// Mitsubishi GX Works2 project: MC-18MR-10MTS-F430-H3G-A例程   PLC: FX3G

PROGRAM MAIN
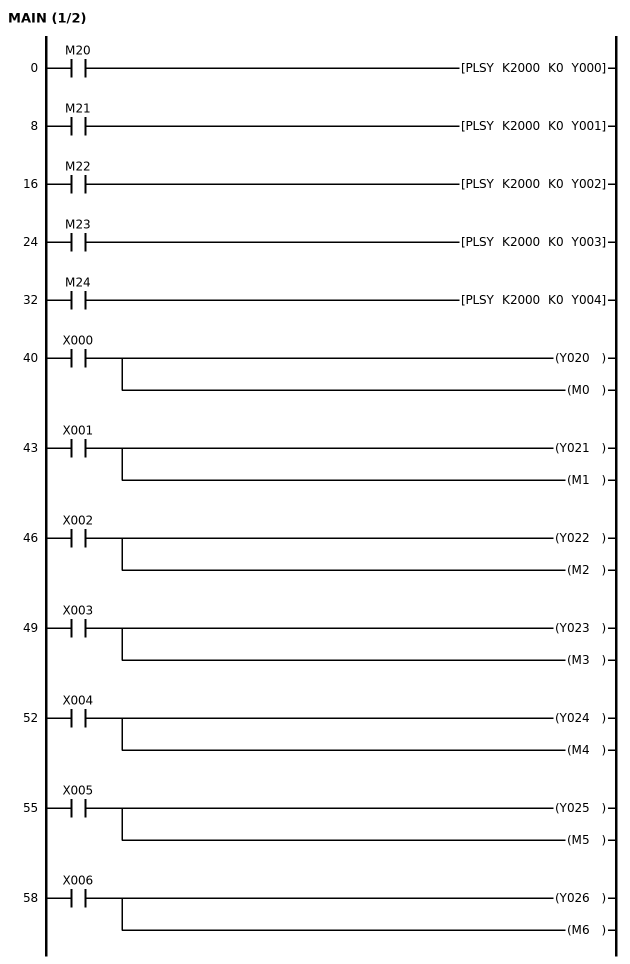
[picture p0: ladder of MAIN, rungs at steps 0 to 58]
0     LD      M20
      PLSY    K2000 K0 Y000
8     LD      M21
      PLSY    K2000 K0 Y001
16    LD      M22
      PLSY    K2000 K0 Y002
24    LD      M23
      PLSY    K2000 K0 Y003
32    LD      M24
      PLSY    K2000 K0 Y004
40    LD      X000
      OUT     Y020
      OUT     M0
43    LD      X001
      OUT     Y021
      OUT     M1
46    LD      X002
      OUT     Y022
      OUT     M2
49    LD      X003
      OUT     Y023
      OUT     M3
52    LD      X004
      OUT     Y024
      OUT     M4
55    LD      X005
      OUT     Y025
      OUT     M5
58    LD      X006
      OUT     Y026
      OUT     M6
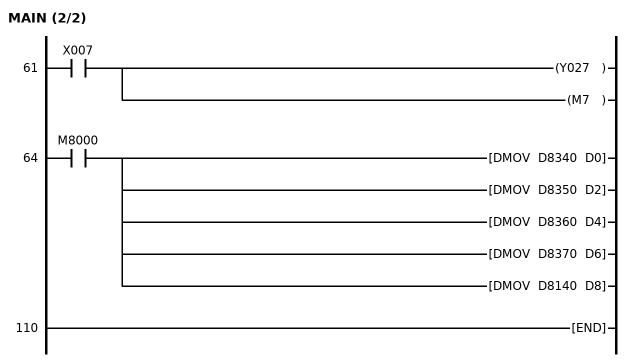
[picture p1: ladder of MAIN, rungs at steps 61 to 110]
61    LD      X007
      OUT     Y027
      OUT     M7
64    LD      M8000
      DMOV    D8340 D0
      DMOV    D8350 D2
      DMOV    D8360 D4
      DMOV    D8370 D6
      DMOV    D8140 D8
110   END
END_PROGRAM
